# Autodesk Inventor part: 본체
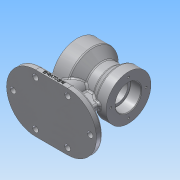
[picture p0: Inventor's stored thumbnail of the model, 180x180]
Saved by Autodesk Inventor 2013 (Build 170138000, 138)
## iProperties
Created: 2020-01
Part Number: 본체
Material: 알루미늄 6061
Document SubType Name: Modeling
Designer: Administrator
Mass: 941.58 g
Surface Area: 654.888 cm^2
Volume: 347.447 cm^3
Density: 2.71 g/cm^3
Author: Administrator
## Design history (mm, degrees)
sketch "스케치1"
  geometry: L1 (-40, 0)-(40, 0); L2 (-40, 0)-(-40, 40); L3 (-40, 40)-(-16, 40); L4 (-16, 40)-(-1.103, 27.5); L5 (-1.103, 27.5)-(13.289, 27.5); L6 (13.289, 27.5)-(24, 35); L7 (24, 35)-(40, 35); L8 (40, 35)-(40, 0); 2 further points
  constraints: 16 end point, 3 perpendicular, 2 parallel, 1 coincident, 1 horizontal, 1 midpoint
  dimensions: "d0" = 80 distance of L1.start L1.end; "d1" = 80 diameter of L3 L1; "d2" = 70 diameter of L7 L1; "d3" = 24 distance of L2.end L3.end; "d4" = 16 distance of L6.end L7.end; "d5" = 55 diameter of L5 L1; "d6" = 40 deg angle of L5 L4; "d7" = 35 deg angle of L6 L5
revolve "회전1" sketch "스케치1" stored, may be unused: angle "d8" = 90 deg
hole "구멍1" diameter "d11" = 32; stored, may be unused: countersink angle "d15" = 90 deg, drill point angle "d17" = 0 deg; dims "d9" = 10, "d10" = 10, "d12" = 6, "d13" = 52, "d14" = 20, "d16" = 63
hole "구멍2" diameter "d20" = 40; stored, may be unused: countersink angle "d24" = 90 deg, drill point angle "d26" = 0 deg; dims "d18" = 10, "d19" = 10, "d21" = 6, "d22" = 52, "d23" = 20, "d25" = 17
fillet "모깎기1" dims "d27" = 0.3, "d31" = 3
chamfer "모따기1" distance "d28" = 1; stored, may be unused: second distance "d29" = 2, angle "d30" = 45 deg
sketch "스케치2"
  geometry: C1 r 40 at (0, 0) reference; 1 further point
  constraints: 1 vertical alignment
  dimensions: "d32" = 33 distance of C1.centre point (0, 33)
hole "구멍3" sketch "스케치2" at (0, 33) diameter "d33" = 3.242; stored, may be unused: countersink angle "d37" = 90 deg, drill point angle "d39" = 118 deg; dims "d34" = 9, "d35" = 52, "d36" = 20, "d38" = 11
sketch "스케치3"
  geometry: C1 r 35 at (0, 0) reference; 1 further point
  constraints: 1 vertical alignment
  dimensions: "d43" = 27.5 distance of C1.centre point (0, 27.5)
hole "구멍4" sketch "스케치3" at (0, 27.5) diameter "d44" = 3.242; stored, may be unused: countersink angle "d48" = 90 deg, drill point angle "d50" = 118 deg; dims "d45" = 9, "d46" = 52, "d47" = 20, "d49" = 11
node "작업 평면1"
sketch "스케치4"
  geometry: L1 (70, -45)-(-70, -45); L2 (-70, -45)-(-70, 45); L3 (-70, 45)-(70, 45); L4 (70, 45)-(70, -45); 3 further points
  constraints: 8 end point, 2 midpoint, 2 parallel, 1 horizontal, 1 horizontal alignment, 1 perpendicular, 1 vertical alignment
  dimensions: "d55" = 140 distance of L2.end L3.end; "d56" = 90 distance of L1.end L2.end
extrude "돌출1" join sketch "스케치4" distance "d57" = 10; taper "d58" = 0 deg
fillet "모깎기2" dims "d59" = 45
sketch "스케치5"
  geometry: L1 (25, 45)-(-25, 45) reference; L2 (-25, -45)-(25, -45) reference; L3 (25, -45)-(-25, -45) reference; L4 (-25, 45)-(25, 45) reference; L5 (-25, 35)-(25, 35); L6 (25, -35)-(-25, -35); C1 r 4.5 at (-60, 0); C2 r 4.5 at (60, 0); C3 r 4.5 at (25, -35); C4 r 4.5 at (-25, -35); C5 r 4.5 at (25, 35); C6 r 4.5 at (-25, 35); A1 r 45 centre (25, 0) between (25, -45) and (25, 45) reference; A2 r 45 centre (-25, 0) between (-25, 45) and (-25, -45) reference; A3 r 45 centre (25, 0) between (25, -45) and (25, 45) reference; A4 r 45 centre (-25, 0) between (-25, 45) and (-25, -45) reference; A5 r 35 centre (-25, 0) between (-25, 35) and (-25, -35); A6 r 35 centre (25, 0) between (25, -35) and (25, 35); 1 further point
  constraints: 8 centre point, 6 point on circle, 4 end point, 4 point on line, 4 vertical alignment, 3 other
  dimensions: "d60" = 10 radial gap between concentric circles of A5 A2; "d61" = 9 diameter of C1; "d62" = 9 diameter of C2; "d64" = 9 diameter of C3; "d65" = 9 diameter of C4; "d66" = 9 diameter of C5; "d67" = 9 diameter of C6
extrude "돌출2" cut sketch "스케치5" stored distance "d68" = 10; taper "d69" = 0 deg
sketch "스케치6"
  geometry: L1 (3.199, 5)-(30, 5); L2 (30, 5)-(30, -5); L3 (30, -5)-(3.199, -5); L4 (40, -35)-(40, 35) reference; A1 r 45 centre (-25, 0) between (-25, 45) and (-25, -45) reference; A2 r 16 centre (-12, 0) between (3.199, 5) and (3.199, -5); 3 further points
  constraints: 6 end point, 3 horizontal alignment, 2 point on circle, 1 centre point, 1 horizontal, 1 midpoint, 1 parallel, 1 perpendicular
  dimensions: "d70" = 32 diameter of A2; "d71" = 42 dimension on A1 A2; "d72" = 10 distance between parallel lines of L3 L1; "d73" = 10 distance between parallel lines of L4 L2
extrude "돌출3" join sketch "스케치6" stored distance "d74" = 10; taper "d75" = 0 deg
fillet "모깎기3" dims "d76" = 3
fillet "모깎기4" dims "d77" = 3
sketch "스케치7"
  geometry: L1 (0, 7)-(0, 7) reference; L2 (0, 7)-(0, 0) reference; L3 (0, 0)-(0, 0) reference; L4 (0, 0)-(0, 7) reference; L5 (-45, 0)-(-45, 7) reference; L6 (95, 0)-(50, 0) reference; 2 further points
  constraints: 1 other
  dimensions: "d78" = 70 distance from line of L5 point (25, 4); "d79" = 4 distance from line of L6 point (25, 4)
feature "엠보싱1" sketch "스케치7" dims "d0" = 80, "d1" = 80, "d2" = 70, "d3" = 24, "d4" = 16, "d5" = 55, "d6" = 40 deg, "d7" = 35 deg, "d80" = 0.5, "d81" = 0
node "솔리드1"
pattern_circular "원형 패턴1" dims angle "d41" = 360 deg
pattern_circular "원형 패턴2" dims angle "d52" = 360 deg
node "투영된 루프1"
node "투영된 루프2"
